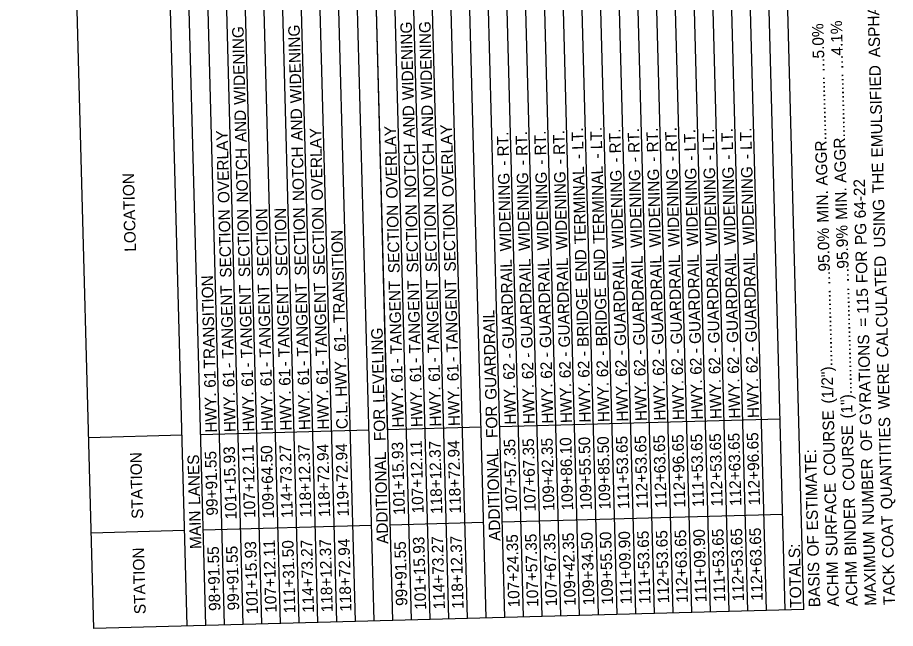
# Model space of a CAD drawing. Extents: x 1930078 to 1931323, y 596452 to 607874.
# Drawn here: x 1930417.5 to 1930875.2, y 603907.4 to 604226 of the extents above; entities that cross this region are included whole.
import ezdxf

# ---------------------------------------------------------------- set-up
doc = ezdxf.new("R2010")
doc.units = 0
doc.layers.add('Default', color=7, linetype='Continuous')

msp = doc.modelspace()

# ---------------------------------------------------------------- linework, layer by layer
at = {"layer": 'Default'}
for p, q in [((1930739.79, 603915.02), (1930700.1, 605393.56)), ((1930749.54, 603915.28), (1930709.85, 605393.82)), ((1930759.28, 603915.54), (1930719.59, 605394.08)), ((1930769.03, 603915.8), (1930729.34, 605394.35)), ((1930778.78, 603916.06), (1930739.09, 605394.61)), ((1930788.52, 603916.33), (1930748.83, 605394.87)), ((1930798.27, 603916.59), (1930758.58, 605395.13)), ((1930808.02, 603916.85), (1930768.33, 605395.39)), ((1930817.76, 603917.11), (1930778.07, 605395.65)), ((1930827.51, 603917.37), (1930787.82, 605395.91)), ((1930574.1, 603910.57), (1930534.41, 605389.11)), ((1930583.85, 603910.83), (1930544.16, 605389.37)), ((1930593.59, 603911.09), (1930553.9, 605389.64)), ((1930603.34, 603911.35), (1930563.65, 605389.9)), ((1930613.09, 603911.62), (1930573.4, 605390.16)), ((1930622.83, 603911.88), (1930583.14, 605390.42)), ((1930632.58, 603912.14), (1930592.89, 605390.68)), ((1930642.33, 603912.4), (1930602.64, 605390.94)), ((1930652.07, 603912.66), (1930612.38, 605391.21)), ((1930661.82, 603912.92), (1930622.13, 605391.47)), ((1930661.82, 603912.92), (1930622.13, 605391.47)), ((1930671.57, 603913.19), (1930631.88, 605391.73)), ((1930681.31, 603913.45), (1930641.62, 605391.99)), ((1930691.06, 603913.71), (1930651.37, 605392.25)), ((1930700.81, 603913.97), (1930661.12, 605392.51)), ((1930710.55, 603914.23), (1930670.86, 605392.78)), ((1930720.3, 603914.49), (1930680.61, 605393.04)), ((1930730.04, 603914.76), (1930690.35, 605393.3)), ((1930457.14, 603907.43), (1930417.45, 605385.97)), ((1930505.88, 603908.74), (1930466.19, 605387.28)), ((1930515.62, 603909), (1930475.93, 605387.54)), ((1930525.37, 603909.26), (1930485.68, 605387.8)), ((1930535.12, 603909.52), (1930495.42, 605388.07)), ((1930544.86, 603909.79), (1930505.17, 605388.33)), ((1930554.61, 603910.05), (1930514.92, 605388.59)), ((1930564.35, 603910.31), (1930524.66, 605388.85)), ((1930603.34, 603911.35), (1930589, 604445.46)), ((1930610.42, 604011.03), (1930604.09, 604246.9)), ((1930815.09, 604016.53), (1930668.9, 604012.6)), ((1930815.09, 604016.53), (1930668.9, 604012.6)), ((1930659.15, 604012.34), (1930610.42, 604011.03)), ((1930659.15, 604012.34), (1930610.42, 604011.03)), ((1930503.21, 604008.15), (1930454.47, 604006.84)), ((1930600.67, 604010.77), (1930512.95, 604008.41)), ((1930600.67, 604010.77), (1930512.95, 604008.41)), ((1930816.43, 603966.82), (1930670.23, 603962.89)), ((1930816.43, 603966.82), (1930670.23, 603962.89)), ((1930602.01, 603961.06), (1930514.29, 603958.71)), ((1930602.01, 603961.06), (1930514.29, 603958.71)), ((1930660.49, 603962.63), (1930611.75, 603961.32)), ((1930660.49, 603962.63), (1930611.75, 603961.32)), ((1930504.54, 603958.45), (1930455.81, 603957.14)), ((1930827.51, 603917.37), (1930457.14, 603907.43)), ((1930827.51, 603917.37), (1930457.14, 603907.43))]:
    msp.add_line(p, q, dxfattribs=at)

# ---------------------------------------------------------------- texts
for s, p in [(' ASPHALT', (1930867.41, 604203.06)), (' WIDENING', (1930565.69, 604179.15)), (' WIDENING', (1930624.17, 604180.72)), (' WIDENING', (1930633.92, 604180.99)), ('5.0%', (1930838.1, 604204.72)), ('4.1%', (1930847.82, 604206.23)), (' WIDENING', (1930536.45, 604178.37)), ('…', (1930838.3, 604197.32)), ('…', (1930848.01, 604198.84)), (' EMULSIFIED', (1930868.81, 604150.89)), (' AGGR...............', (1930839.94, 604136.14)), (' AGGR...............', (1930849.66, 604137.66)), (' AND', (1930536.98, 604158.79)), (' AND', (1930566.22, 604159.58)), (' AND', (1930624.7, 604161.15)), (' AND', (1930634.44, 604161.41)), (' OVERLAY', (1930528.07, 604127.08)), (' OVERLAY', (1930576.81, 604128.39)), (' OVERLAY', (1930615.79, 604129.44)), (' OVERLAY', (1930645.03, 604130.22)), (' LT.', (1930712.64, 604154.9)), (' LT.', (1930722.39, 604155.16)), (' RT.', (1930732.2, 604152.99)), (' RT.', (1930741.95, 604153.25)), (' RT.', (1930751.7, 604153.51)), (' RT.', (1930761.44, 604153.78)), (' LT.', (1930771.19, 604154.04)), (' LT.', (1930780.94, 604154.3)), (' LT.', (1930790.68, 604154.56)), (' LT.', (1930800.43, 604154.82)), (' RT.', (1930673.72, 604151.42)), (' RT.', (1930683.47, 604151.68)), (' RT.', (1930693.22, 604151.94)), (' RT.', (1930702.96, 604152.21)), (' NOTCH', (1930567.06, 604128.13)), (' NOTCH', (1930625.54, 604129.7)), (' NOTCH', (1930635.29, 604129.96)), (' NOTCH', (1930537.82, 604127.35)), (' -', (1930712.77, 604150.04)), (' -', (1930722.52, 604150.31)), (' -', (1930751.83, 604148.66)), (' -', (1930761.57, 604148.92)), (' -', (1930771.32, 604149.18)), (' -', (1930781.07, 604149.44)), (' -', (1930790.81, 604149.71)), (' -', (1930800.56, 604149.97)), (' -', (1930673.85, 604146.57)), (' -', (1930683.6, 604146.83)), (' -', (1930693.35, 604147.09)), (' -', (1930703.09, 604147.35)), (' TERMINAL', (1930723.71, 604105.9)), (' -', (1930732.33, 604148.14)), (' -', (1930742.08, 604148.4)), (' THE', (1930869.31, 604132.24)), ('LOCATION', (1930479.25, 604103.97)), (' WIDENING', (1930675.05, 604101.93)), (' WIDENING', (1930684.8, 604102.2)), (' WIDENING', (1930694.55, 604102.46)), (' WIDENING', (1930704.29, 604102.72)), (' TERMINAL', (1930713.97, 604105.64)), (' WIDENING', (1930733.53, 604103.5)), (' WIDENING', (1930743.28, 604103.77)), (' WIDENING', (1930753.02, 604104.03)), (' WIDENING', (1930762.77, 604104.29)), (' WIDENING', (1930772.52, 604104.55)), (' WIDENING', (1930782.26, 604104.81)), (' WIDENING', (1930792.01, 604105.07)), (' WIDENING', (1930801.76, 604105.34)), (' 64-22', (1930859.91, 604119.14)), (' MIN.', (1930840.46, 604116.86)), (' MIN.', (1930850.17, 604118.37)), (' USING', (1930870.07, 604103.9)), (' SECTION', (1930538.86, 604088.45)), (' SECTION', (1930548.61, 604088.71)), (' SECTION', (1930558.36, 604088.98)), (' SECTION', (1930568.1, 604089.24)), (' SECTION', (1930577.85, 604089.5)), (' SECTION', (1930616.84, 604090.55)), (' SECTION', (1930626.58, 604090.81)), (' SECTION', (1930636.33, 604091.07)), (' SECTION', (1930646.08, 604091.33)), (' SECTION', (1930529.12, 604088.19)), ('95.9%', (1930850.8, 604095.14)), (' PG', (1930860.28, 604105.23)), (' TRANSITION', (1930588.28, 604064.52)), ('95.0%', (1930841.08, 604093.63)), (' END', (1930714.49, 604086.07)), (' END', (1930724.24, 604086.33)), (' GUARDRAIL', (1930783.63, 604053.89)), (' GUARDRAIL', (1930793.38, 604054.15)), (' GUARDRAIL', (1930803.12, 604054.41)), (' FOR', (1930860.81, 604085.32)), (' GUARDRAIL', (1930676.42, 604051.01)), (' GUARDRAIL', (1930686.17, 604051.27)), (' GUARDRAIL', (1930695.91, 604051.53)), (' GUARDRAIL', (1930705.66, 604051.79)), (' GUARDRAIL', (1930734.9, 604052.58)), (' GUARDRAIL', (1930744.64, 604052.84)), (' GUARDRAIL', (1930754.39, 604053.1)), (' GUARDRAIL', (1930764.14, 604053.36)), (' GUARDRAIL', (1930773.88, 604053.62)), (' CALCULATED', (1930871.61, 604046.6)), ('…', (1930851, 604087.74)), (' TRANSITION', (1930520.64, 604040.87)), (' TANGENT', (1930637.46, 604048.86)), (' TANGENT', (1930647.21, 604049.13)), ('…', (1930841.28, 604086.23)), (' TANGENT', (1930530.25, 604045.99)), (' TANGENT', (1930540, 604046.25)), (' TANGENT', (1930549.74, 604046.51)), (' TANGENT', (1930559.49, 604046.77)), (' TANGENT', (1930569.24, 604047.03)), (' TANGENT', (1930578.98, 604047.29)), (' TANGENT', (1930617.97, 604048.34)), (' TANGENT', (1930627.72, 604048.6)), (' BRIDGE', (1930715.41, 604052.05)), (' BRIDGE', (1930725.15, 604052.32)), (' (1").........................', (1930852.96, 604014.76)), (' 115', (1930861.24, 604069.35)), (' (1/2")..................', (1930842.99, 604022.55)), (' GUARDRAIL', (1930667.38, 604024.52)), (' =', (1930861.42, 604062.6)), (' -', (1930588.41, 604059.66)), (' LEVELING', (1930608.9, 604022.95)), (' 61', (1930588.68, 604049.56)), (' GYRATIONS', (1930862.8, 604011.35)), (' -', (1930735.03, 604047.72)), (' -', (1930744.78, 604047.98)), (' -', (1930754.52, 604048.25)), (' -', (1930764.27, 604048.51)), (' -', (1930774.01, 604048.77)), (' -', (1930783.76, 604049.03)), (' -', (1930793.51, 604049.29)), (' -', (1930803.25, 604049.55)), (' HWY.', (1930589.31, 604026.08)), (' -', (1930618.1, 604043.49)), (' -', (1930627.85, 604043.75)), (' -', (1930637.59, 604044.01)), (' -', (1930647.34, 604044.27)), (' -', (1930676.55, 604046.15)), (' -', (1930686.3, 604046.41)), (' -', (1930696.04, 604046.68)), (' -', (1930705.79, 604046.94)), (' -', (1930715.54, 604047.2)), (' -', (1930725.28, 604047.46)), (' 62', (1930754.82, 604037.05)), (' 62', (1930764.57, 604037.31)), (' 62', (1930774.32, 604037.57)), (' 62', (1930784.06, 604037.83)), (' 62', (1930793.81, 604038.09)), (' 62', (1930803.55, 604038.35)), (' -', (1930530.38, 604041.13)), (' -', (1930540.13, 604041.39)), (' -', (1930549.87, 604041.65)), (' -', (1930559.62, 604041.92)), (' -', (1930569.37, 604042.18)), (' 61', (1930579.39, 604032.34)), (' -', (1930579.11, 604042.44)), (' 61', (1930618.37, 604033.38)), (' 61', (1930628.12, 604033.64)), (' 61', (1930637.86, 604033.91)), (' 61', (1930647.61, 604034.17)), (' 62', (1930676.85, 604034.95)), (' 62', (1930686.6, 604035.21)), (' 62', (1930696.34, 604035.48)), (' 62', (1930706.09, 604035.74)), (' 62', (1930715.84, 604036)), (' 62', (1930725.58, 604036.26)), (' 62', (1930735.33, 604036.52)), (' 62', (1930745.08, 604036.78)), (' WERE', (1930872.33, 604019.58)), (' 61', (1930520.91, 604030.77)), (' 61', (1930530.65, 604031.03)), (' 61', (1930540.4, 604031.29)), (' 61', (1930550.15, 604031.55)), (' 61', (1930559.89, 604031.81)), (' 61', (1930569.64, 604032.07)), ('HWY.', (1930677.42, 604013.8)), ('HWY.', (1930687.16, 604014.07)), ('HWY.', (1930696.91, 604014.33)), ('HWY.', (1930706.66, 604014.59)), ('HWY.', (1930716.4, 604014.85)), ('HWY.', (1930726.15, 604015.11)), ('HWY.', (1930735.9, 604015.37)), ('HWY.', (1930745.64, 604015.64)), ('HWY.', (1930755.39, 604015.9)), ('HWY.', (1930765.14, 604016.16)), ('HWY.', (1930774.88, 604016.42)), ('HWY.', (1930784.63, 604016.68)), ('HWY.', (1930794.38, 604016.94)), ('HWY.', (1930804.12, 604017.21)), ('HWY.', (1930521.47, 604009.62)), ('HWY.', (1930531.22, 604009.88)), ('HWY.', (1930540.97, 604010.14)), ('HWY.', (1930550.71, 604010.4)), ('HWY.', (1930560.46, 604010.67)), ('HWY.', (1930570.21, 604010.93)), ('HWY.', (1930579.95, 604011.19)), ('HWY.', (1930618.94, 604012.23)), ('HWY.', (1930628.69, 604012.5)), ('HWY.', (1930638.43, 604012.76)), ('HWY.', (1930648.18, 604013.02)), ('C.L.', (1930589.7, 604011.45)), (' FOR', (1930609.43, 604002.97)), (' FOR', (1930667.91, 604004.54)), (' COURSE', (1930844.01, 603984.81)), (' QUANTITIES', (1930873.73, 603967.4)), (' COURSE', (1930853.97, 603977.03)), ('109+42.35', (1930697.46, 603968.73)), ('109+86.10', (1930707.21, 603969.03)), ('109+55.50', (1930716.95, 603969.29)), ('109+85.50', (1930726.7, 603969.55)), ('111+53.65', (1930736.45, 603969.78)), ('112+53.65', (1930746.19, 603970.04)), ('112+63.65', (1930755.94, 603970.3)), ('112+96.65', (1930765.69, 603970.57)), ('111+53.65', (1930775.43, 603970.83)), ('112+53.65', (1930785.18, 603971.09)), ('112+63.65', (1930794.92, 603971.35)), ('112+96.65', (1930804.67, 603971.61)), (' OF', (1930863.17, 603997.77)), ('101+15.93', (1930531.77, 603964.31)), ('107+12.11', (1930541.5, 603965.15)), ('109+64.50', (1930551.26, 603964.84)), ('114+73.27', (1930561.01, 603965.09)), ('118+12.37', (1930570.75, 603965.36)), ('118+72.94', (1930580.5, 603965.63)), ('119+72.94', (1930590.25, 603965.89)), ('101+15.93', (1930619.49, 603966.66)), ('107+12.11', (1930629.22, 603967.51)), ('118+12.37', (1930638.98, 603967.19)), ('118+72.94', (1930648.73, 603967.46)), ('107+57.35', (1930677.97, 603968.21)), ('107+67.35', (1930687.71, 603968.47)), ('STATION', (1930482.99, 603964.67)), (' LANES', (1930512.79, 603969.67)), ('99+91.55', (1930521.96, 603966.35)), ('ADDITIONAL', (1930610.81, 603951.55)), ('ADDITIONAL', (1930669.29, 603953.11)), (' ESTIMATE:', (1930835.01, 603956.41)), (' NUMBER', (1930864.2, 603959.23)), (' SURFACE', (1930845.13, 603942.88)), (' BINDER', (1930854.88, 603943.15)), ('MAIN', (1930513.35, 603948.93)), (' COAT', (1930874.42, 603941.96)), ('107+24.35', (1930679.3, 603918.5)), ('107+57.35', (1930689.05, 603918.77)), ('107+67.35', (1930698.79, 603919.03)), ('109+42.35', (1930708.54, 603919.29)), ('109+34.50', (1930718.29, 603919.59)), ('109+55.50', (1930728.03, 603919.85)), ('111+09.90', (1930737.78, 603920.11)), ('111+53.65', (1930747.53, 603920.34)), ('112+53.65', (1930757.27, 603920.6)), ('112+63.65', (1930767.02, 603920.86)), ('111+09.90', (1930776.76, 603921.16)), ('111+53.65', (1930786.51, 603921.38)), ('112+53.65', (1930796.26, 603921.64)), ('112+63.65', (1930806.01, 603921.91)), ('MAXIMUM', (1930865.27, 603919.36)), ('101+15.93', (1930542.85, 603914.86)), ('107+12.11', (1930552.58, 603915.71)), ('111+31.50', (1930562.34, 603915.4)), ('114+73.27', (1930572.09, 603915.65)), ('118+12.37', (1930581.84, 603915.91)), ('118+72.94', (1930591.58, 603916.19)), ('99+91.55', (1930620.76, 603919.26)), ('101+15.93', (1930630.57, 603917.22)), ('114+73.27', (1930640.31, 603917.48)), ('118+12.37', (1930650.06, 603917.74)), (' OF', (1930835.38, 603942.83)), ('STATION', (1930484.33, 603914.96)), ('98+91.55', (1930523.29, 603916.65)), ('99+91.55', (1930533.04, 603916.91)), ('TOTALS:', (1930826.28, 603918.32)), ('BASIS', (1930836.03, 603918.58)), ('ACHM', (1930845.78, 603918.84)), ('ACHM', (1930855.52, 603919.1)), ('TACK', (1930875.02, 603919.62))]:
    msp.add_text(s, height=6, rotation=91.5377, dxfattribs=at).set_placement(p)

doc.saveas('drawing.dxf')
